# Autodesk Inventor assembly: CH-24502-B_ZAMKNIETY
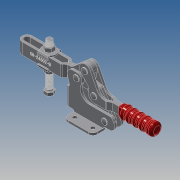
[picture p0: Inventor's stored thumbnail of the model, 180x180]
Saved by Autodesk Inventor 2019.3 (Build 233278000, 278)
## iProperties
Company: ·L?¤¤?
Created: 2010-06
Part Number: CH-24502-B_ZAMKNIETY
Material: Ogólny
Description: STEP AP203
Document SubType Name: Assembly
Designer: CADENGINEERING4
Sending System: SolidWorks 2005179
Preprocessor: SwSTEP 2.0
Title: CH-24502-B.STEP
Author: ·L?¥Î?
Revision Number: ANY
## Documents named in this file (11)
- E:\STRONA\Horizontal toggle clamp\CH-24502-B\CH-24502-B_ZAMKNIETY.iam
- E:\STRONA\Horizontal toggle clamp\CH-24502-B\FW120___.ipt
- E:\STRONA\Horizontal toggle clamp\CH-24502-B\CH-24502-B-06___.ipt
- E:\STRONA\Horizontal toggle clamp\CH-24502-B\CH-24502-B-05___.ipt
- E:\STRONA\Horizontal toggle clamp\CH-24502-B\101-J-06___.ipt
- E:\STRONA\Horizontal toggle clamp\CH-24502-B\CH-SA-121017___.ipt
- E:\STRONA\Horizontal toggle clamp\CH-24502-B\M12___.ipt
- E:\STRONA\Horizontal toggle clamp\CH-24502-B\CH-24502-B-02___.ipt
- E:\STRONA\Horizontal toggle clamp\CH-24502-B\CH-24502-B-01___.ipt
- E:\STRONA\Horizontal toggle clamp\CH-24502-B\CH-24502-B-03___.ipt
- E:\STRONA\Horizontal toggle clamp\CH-24502-B\CH-24502-B-04___.ipt
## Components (17 placed, 17 different names)
1. FW120_??_1 — Równoległe:1, Zestawiające:10, Zestawiające:11, Zestawiające:13
2. CH-24502-B-06_??_2 — Zestawiające:1, Zestawiające:2, Zestawiające:3
3. CH-24502-B-05_??_3 — Zestawiające:19, Zestawiające:20
4. 101-J-06_??_4 — Równoległe:3, Zestawiające:27, Zestawiające:36, Zestawiające:37
5. CH-SA-121017_??_5 — Zestawiające:5, Zestawiające:7, Równoległe:2, Zestawiające:10, Zestawiające:12, Zestawiające:14
6. FW120_??_6 — Zestawiające:4, Zestawiające:5, Zestawiające:6, Równoległe:1, Zestawiające:8, Zestawiające:9
7. CH-24502-B-05_??_7 — Zestawiające:30, Zestawiające:31
8. M12_??_8 — Zestawiające:7, Zestawiające:8, Równoległe:2
9. CH-24502-B-02_??_9 — Zestawiające:4, Zestawiające:6, Zestawiające:9, Zestawiające:11, Zestawiające:14, Zestawiające:17, Zestawiające:18, Równoległe:3, Zestawiające:27, Zestawiające:39
10. CH-24502-B-05_??_10 — Zestawiające:37, Zestawiające:38
11. CH-24502-B-01_??_11 — Zestawiające:15, Zestawiające:16, Zestawiające:17, Zestawiające:18, Zestawiające:19, Zestawiające:20, Zestawiające:26, Zestawiające:28, Zestawiające:29, Zestawiające:30, Zestawiające:31
12. CH-24502-B-05_??_12 — Zestawiające:34, Zestawiające:35
13. CH-24502-B-03_??_13 — Zestawiające:1, Zestawiające:2, Zestawiające:3, Zestawiające:32, Zestawiające:33, Zestawiające:34, Zestawiające:35, Zestawiające:36, Zestawiające:38
14. M12_??_14 — Zestawiające:12, Zestawiające:13
15. CH-24502-B-04_??_15 — Zestawiające:23, Zestawiające:24, Zestawiające:25
16. CH-24502-B-04_??_16 — Zestawiające:23, Zestawiające:24, Zestawiające:25, Zestawiające:26, Zestawiające:28, Zestawiające:29, Zestawiające:32, Zestawiające:33, Zestawiające:39
17. 101-J-06_??_17 — Zestawiające:15, Zestawiające:16
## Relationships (40: Mate 37, Flush 3)
- Zestawiające:1 [Mate]: CH-24502-B-06_??_2 ↔ CH-24502-B-03_??_13
- Zestawiające:2 [Mate]: CH-24502-B-06_??_2 ↔ CH-24502-B-03_??_13
- Zestawiające:3 [Mate]: CH-24502-B-06_??_2 ↔ CH-24502-B-03_??_13
- Zestawiające:4 [Mate]: FW120_??_6 ↔ CH-24502-B-02_??_9
- Zestawiające:5 [Mate]: CH-SA-121017_??_5 ↔ FW120_??_6
- Zestawiające:6 [Mate]: FW120_??_6 ↔ CH-24502-B-02_??_9
- Równoległe:1 [Flush]: FW120_??_1 ↔ FW120_??_6
- Zestawiające:7 [Mate]: CH-SA-121017_??_5 ↔ M12_??_8
- Zestawiające:8 [Mate]: FW120_??_6 ↔ M12_??_8
- Równoległe:2 [Flush]: CH-SA-121017_??_5 ↔ M12_??_8
- Zestawiające:9 [Mate]: FW120_??_6 ↔ CH-24502-B-02_??_9
- Zestawiające:10 [Mate]: FW120_??_1 ↔ CH-SA-121017_??_5
- Zestawiające:11 [Mate]: FW120_??_1 ↔ CH-24502-B-02_??_9
- Zestawiające:12 [Mate]: CH-SA-121017_??_5 ↔ M12_??_14
- Zestawiające:13 [Mate]: FW120_??_1 ↔ M12_??_14
- Zestawiające:14 [Mate]: CH-SA-121017_??_5 ↔ CH-24502-B-02_??_9
- Zestawiające:15 [Mate]: CH-24502-B-01_??_11 ↔ 101-J-06_??_17
- Zestawiające:16 [Mate]: CH-24502-B-01_??_11 ↔ 101-J-06_??_17
- Zestawiające:17 [Mate]: CH-24502-B-02_??_9 ↔ CH-24502-B-01_??_11
- Zestawiające:18 [Mate]: CH-24502-B-02_??_9 ↔ CH-24502-B-01_??_11
- Zestawiające:19 [Mate]: CH-24502-B-05_??_3 ↔ CH-24502-B-01_??_11
- Zestawiające:20 [Mate]: CH-24502-B-05_??_3 ↔ CH-24502-B-01_??_11
- Zestawiające:23 [Mate]: CH-24502-B-04_??_15 ↔ CH-24502-B-04_??_16
- Zestawiające:24 [Mate]: CH-24502-B-04_??_15 ↔ CH-24502-B-04_??_16
- Zestawiające:25 [Mate]: CH-24502-B-04_??_15 ↔ CH-24502-B-04_??_16
- Zestawiające:26 [Mate]: CH-24502-B-01_??_11 ↔ CH-24502-B-04_??_16
- Równoległe:3 [Flush]: 101-J-06_??_4 ↔ CH-24502-B-02_??_9
- Zestawiające:27 [Mate]: 101-J-06_??_4 ↔ CH-24502-B-02_??_9
- Zestawiające:28 [Mate]: CH-24502-B-01_??_11 ↔ CH-24502-B-04_??_16
- Zestawiające:29 [Mate]: CH-24502-B-01_??_11 ↔ CH-24502-B-04_??_16
- Zestawiające:30 [Mate]: CH-24502-B-05_??_7 ↔ CH-24502-B-01_??_11
- Zestawiające:31 [Mate]: CH-24502-B-05_??_7 ↔ CH-24502-B-01_??_11
- Zestawiające:32 [Mate]: CH-24502-B-03_??_13 ↔ CH-24502-B-04_??_16
- Zestawiające:33 [Mate]: CH-24502-B-03_??_13 ↔ CH-24502-B-04_??_16
- Zestawiające:34 [Mate]: CH-24502-B-05_??_12 ↔ CH-24502-B-03_??_13
- Zestawiające:35 [Mate]: CH-24502-B-05_??_12 ↔ CH-24502-B-03_??_13
- Zestawiające:36 [Mate]: 101-J-06_??_4 ↔ CH-24502-B-03_??_13
- Zestawiające:37 [Mate]: 101-J-06_??_4 ↔ CH-24502-B-05_??_10
- Zestawiające:38 [Mate]: CH-24502-B-05_??_10 ↔ CH-24502-B-03_??_13
- Zestawiające:39 [Mate]: CH-24502-B-02_??_9 ↔ CH-24502-B-04_??_16
